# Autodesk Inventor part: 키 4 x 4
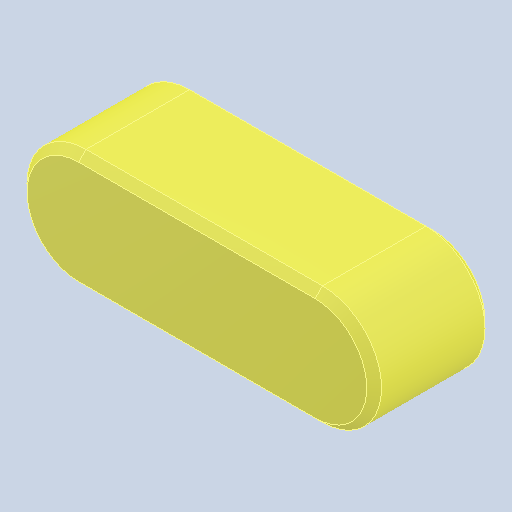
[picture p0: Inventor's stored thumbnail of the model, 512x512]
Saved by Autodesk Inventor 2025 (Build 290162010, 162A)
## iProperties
Created: 2024-08
Part Number: 키 4 x 4
Material: 강철, 연강
Description: 키 및 해당 키홈
Document SubType Name: Modeling
Designer: 학생
Density: 7.86 g/cm^3
Appearance: 기본값
Author: jhkim
Sending System: Autodesk Inventor 2025
Preprocessor: ST-DEVELOPER v20
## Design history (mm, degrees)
feature "Solid1"
node "솔리드1"
